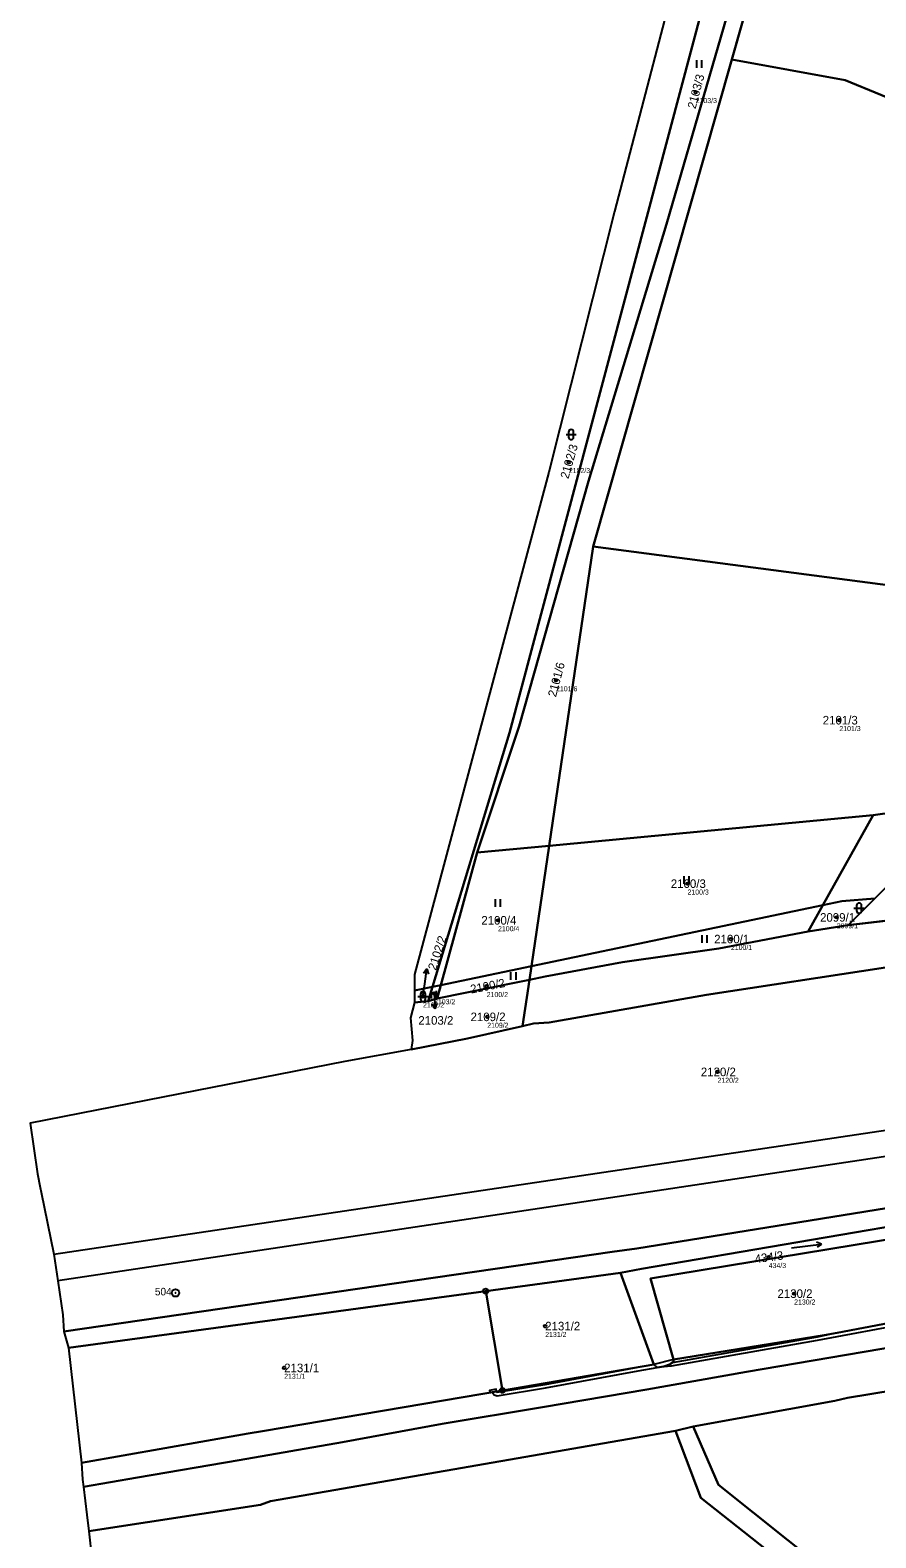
# Model space of a CAD drawing. Extents: x -754731 to -751381, y -1060564 to -1058101.
# Drawn here: x -754402.3 to -754234.5, y -1059330.4 to -1059031.3 of the extents above; entities that cross this region are included whole.
import ezdxf

# ---------------------------------------------------------------- set-up
doc = ezdxf.new("R2010")
doc.units = 0
for name, color, linetype in [('Definiční body', 7, 'Continuous'), ('Hranice parcel', 7, 'Continuous'), ('Parcelní čísla', 7, 'Continuous'), ('Polygon ku', 7, 'Continuous'), ('Polygon parcely', 7, 'Continuous'), ('Pop  PČ popisy', 7, 'Continuous'), ('Poz předměty', 7, 'Continuous'), ('Věcná břemena k části', 7, 'Continuous'), ('Značky bodu BP', 7, 'Continuous'), ('Značky kultur', 7, 'Continuous')]:
    doc.layers.add(name, color=color, linetype=linetype)

msp = doc.modelspace()

# ---------------------------------------------------------------- linework, layer by layer
at = {"layer": 'Definiční body'}
for centre in [(-754270.23, -1059043.64), (-754295.4, -1059117.02), (-754297.93, -1059160.29), (-754241.71, -1059168.19), (-754271.85, -1059200.61), (-754309.45, -1059207.88), (-754242.23, -1059207.3), (-754263.24, -1059211.6), (-754324.34, -1059223), (-754322.15, -1059222.37), (-754311.69, -1059220.94), (-754311.59, -1059227.03), (-754265.89, -1059237.94), (-754255.74, -1059274.68), (-754250.69, -1059281.92), (-754300.09, -1059288.36), (-754351.89, -1059296.65)]:
    msp.add_circle(centre, 0.25, dxfattribs=at)
at = {"layer": 'Hranice parcel'}
for p, q in [((-754263.03, -1059037.17), (-754254.03, -1059005.48)), ((-754263.03, -1059037.17), (-754290.54, -1059133.76)), ((-754290.54, -1059133.76), (-754299.3, -1059193.09)), ((-754235, -1059187), (-754299.3, -1059193.09)), ((-754235, -1059187), (-754244.98, -1059204.86)), ((-754299.3, -1059193.09), (-754313.6, -1059194.45)), ((-754299.3, -1059193.09), (-754302.83, -1059216.97)), ((-754313.6, -1059194.45), (-754320.79, -1059220.73)), ((-754244.98, -1059204.86), (-754302.83, -1059216.97)), ((-754247.92, -1059210.12), (-754244.98, -1059204.86)), ((-754234.68, -1059203.56), (-754239.97, -1059208.82)), ((-754226.15, -1059207.23), (-754239.97, -1059208.82)), ((-754239.97, -1059208.82), (-754247.92, -1059210.12)), ((-754302.83, -1059216.97), (-754320.79, -1059220.73)), ((-754302.83, -1059216.97), (-754303.23, -1059219.67)), ((-754326.05, -1059218.65), (-754326.02, -1059221.83)), ((-754303.23, -1059219.67), (-754304.59, -1059228.85)), ((-754322.45, -1059221.08), (-754326.02, -1059221.83)), ((-754326.02, -1059221.83), (-754326, -1059224.2)), ((-754323.3, -1059223.9), (-754322.45, -1059221.08)), ((-754320.79, -1059220.73), (-754322.45, -1059221.08)), ((-754320.79, -1059220.73), (-754321.51, -1059223.38)), ((-754326, -1059224.2), (-754323.3, -1059223.9)), ((-754323.3, -1059223.9), (-754321.51, -1059223.38)), ((-754326.7, -1059233.52), (-754339.87, -1059235.85)), ((-754339.87, -1059235.85), (-754402.3, -1059248.1)), ((-754400.29, -1059260.85), (-754400.1, -1059261.79)), ((-754311.9, -1059281.41), (-754285.15, -1059277.78)), ((-754285.15, -1059277.78), (-754278.5, -1059296)), ((-754394.66, -1059292.65), (-754311.9, -1059281.41)), ((-754311.9, -1059281.41), (-754308.57, -1059301.11)), ((-754395.79, -1059286.13), (-754395.64, -1059289.45)), ((-754395.64, -1059289.45), (-754394.66, -1059292.65)), ((-754394.66, -1059292.65), (-754392.12, -1059315.49)), ((-754278.5, -1059296), (-754308.57, -1059301.11)), ((-754270.7, -1059308.3), (-754274.2, -1059309.1))]:
    msp.add_line(p, q, dxfattribs=at)
for points in [[(-754259.3, -1058966), (-754271.04, -1059008.8), (-754286.33, -1059067.3), (-754299.4, -1059119), (-754326.05, -1059218.65)], [(-754322.45, -1059221.08), (-754307.2, -1059170.7), (-754252.93, -1058966.94)], [(-754246.61, -1058967.88), (-754248.9, -1058975.5), (-754261.8, -1059020.8), (-754276.05, -1059069.8), (-754291.5, -1059120.8), (-754305.25, -1059169.4), (-754313.6, -1059194.45)], [(-754019.45, -1059118.18), (-754049.17, -1059107.78), (-754115.6, -1059087.15), (-754134.83, -1059085.59), (-754158.57, -1059073.81), (-754175.73, -1059069.12), (-754183.13, -1059057.84), (-754196.56, -1059048.53), (-754203.79, -1059063.52), (-754219.32, -1059050), (-754240.59, -1059041.26), (-754263.03, -1059037.17)], [(-754145.31, -1059167.71), (-754162.03, -1059164.03), (-754187.61, -1059153.26), (-754229.57, -1059141.76), (-754290.54, -1059133.76)], [(-754145.31, -1059167.71), (-754156.78, -1059170.93), (-754188.7, -1059180.8), (-754210.5, -1059183.6), (-754235, -1059187)], [(-754215, -1059193.4), (-754228.6, -1059197.5), (-754234.68, -1059203.56)], [(-754234.68, -1059203.56), (-754241.21, -1059204.07), (-754244.98, -1059204.86)], [(-754141.04, -1059210.29), (-754152.39, -1059210.46), (-754177.1, -1059212.37), (-754232.58, -1059217.23), (-754268.09, -1059222.66), (-754299.29, -1059228.13), (-754302.4, -1059228.35), (-754304.59, -1059228.85)], [(-754303.23, -1059219.67), (-754300.09, -1059219.03), (-754284.78, -1059216.19), (-754265.65, -1059213.48), (-754247.92, -1059210.12)], [(-754321.51, -1059223.38), (-754305.55, -1059220.14), (-754303.23, -1059219.67)], [(-754326, -1059224.2), (-754326.8, -1059227.25), (-754326.4, -1059231.7), (-754326.7, -1059233.52)], [(-754304.59, -1059228.85), (-754315.51, -1059231.32), (-754326.7, -1059233.52)], [(-753994.92, -1059229.37), (-754009.03, -1059236.26), (-754028.95, -1059245.78), (-754072.1, -1059264.36), (-754105.59, -1059276.18), (-754143.83, -1059285.35), (-754183.72, -1059293.33), (-754240.08, -1059302.61), (-754242.58, -1059303.17), (-754270.7, -1059308.3)], [(-754395.64, -1059289.45), (-754286.8, -1059273.6), (-754281.9, -1059273), (-754184.89, -1059257.29), (-754159.27, -1059253.23), (-754150.1, -1059252.43), (-754137.76, -1059249.13), (-754127.95, -1059247.01)], [(-754402.3, -1059248.1), (-754400.84, -1059258.13), (-754400.29, -1059260.85)], [(-754400.1, -1059261.79), (-754397.6, -1059274.1), (-754396.8, -1059279.4), (-754395.79, -1059286.13)], [(-754218.94, -1059266.4), (-754280.99, -1059277), (-754285.15, -1059277.78)], [(-754218.5, -1059268.95), (-754279.2, -1059278.9), (-754274.6, -1059295)], [(-754222.65, -1059285.97), (-754242.14, -1059289.7), (-754244.73, -1059290.17), (-754274.6, -1059295)], [(-754391.74, -1059320.25), (-754381.02, -1059318.4), (-754360.81, -1059314.93), (-754340.34, -1059311.35), (-754320.54, -1059307.74), (-754300.64, -1059304.45), (-754279.95, -1059300.92), (-754260.12, -1059297.43), (-754240.31, -1059294.04), (-754219.65, -1059290.55)], [(-754274.6, -1059295), (-754274.65, -1059295.4), (-754275.4, -1059296), (-754276.57, -1059296.4), (-754277.9, -1059296.6), (-754278.5, -1059296)], [(-754308.57, -1059301.11), (-754356.2, -1059309.2), (-754359.03, -1059309.65), (-754392.12, -1059315.49)], [(-754274.2, -1059309.1), (-754354.6, -1059323.1), (-754356.6, -1059323.8), (-754390.66, -1059329.03)], [(-754274.2, -1059309.1), (-754269.21, -1059322.4), (-754185.4, -1059388.65), (-754163.23, -1059405.65), (-754156.7, -1059409.63), (-754173.89, -1059415.19), (-754189.15, -1059420.39), (-754205.85, -1059428.31), (-754239.13, -1059438.35), (-754268.85, -1059442.06), (-754301.09, -1059445.19), (-754332.05, -1059446.78), (-754377.1, -1059447.2)], [(-754270.7, -1059308.3), (-754265.68, -1059319.84), (-754182.48, -1059386.19), (-754157.97, -1059399.94), (-754148.14, -1059406.2), (-754014.2, -1059355.81)], [(-754392.12, -1059315.49), (-754391.92, -1059318.76), (-754391.74, -1059320.25)], [(-754391.74, -1059320.25), (-754391.08, -1059325.77), (-754390.66, -1059329.03)], [(-754390.66, -1059329.03), (-754385.87, -1059372.37), (-754377.1, -1059447.2)]]:
    msp.add_lwpolyline(points, dxfattribs=at)
at = {"layer": 'Polygon ku'}
msp.add_lwpolyline([(-754271.04, -1059008.8), (-754286.33, -1059067.3), (-754299.4, -1059119), (-754326.05, -1059218.65), (-754326.02, -1059221.83), (-754326, -1059224.2), (-754326.8, -1059227.25), (-754326.4, -1059231.7), (-754326.7, -1059233.52), (-754339.87, -1059235.85), (-754402.3, -1059248.1), (-754400.84, -1059258.13), (-754400.29, -1059260.85), (-754400.1, -1059261.79), (-754397.6, -1059274.1), (-754396.8, -1059279.4), (-754395.79, -1059286.13), (-754395.64, -1059289.45), (-754394.66, -1059292.65), (-754392.12, -1059315.49), (-754391.92, -1059318.76), (-754391.74, -1059320.25), (-754391.08, -1059325.77), (-754390.66, -1059329.03), (-754385.87, -1059372.37)], dxfattribs=at)
at = {"layer": 'Polygon parcely'}
for points in [[(-754326.05, -1059218.65), (-754326.02, -1059221.83), (-754322.45, -1059221.08), (-754307.2, -1059170.7), (-754252.93, -1058966.94), (-754259.3, -1058966), (-754271.04, -1059008.8), (-754286.33, -1059067.3), (-754299.4, -1059119)], [(-754252.93, -1058966.94), (-754307.2, -1059170.7), (-754322.45, -1059221.08), (-754320.79, -1059220.73), (-754313.6, -1059194.45), (-754305.25, -1059169.4), (-754291.5, -1059120.8), (-754276.05, -1059069.8), (-754261.8, -1059020.8), (-754248.9, -1058975.5), (-754246.61, -1058967.88)], [(-754291.5, -1059120.8), (-754305.25, -1059169.4), (-754313.6, -1059194.45), (-754299.3, -1059193.09), (-754290.54, -1059133.76), (-754263.03, -1059037.17), (-754254.03, -1059005.48), (-754243.49, -1058968.34), (-754246.61, -1058967.88), (-754248.9, -1058975.5), (-754261.8, -1059020.8), (-754276.05, -1059069.8)], [(-754019.45, -1059118.18), (-754049.17, -1059107.78), (-754115.6, -1059087.15), (-754134.83, -1059085.59), (-754158.57, -1059073.81), (-754175.73, -1059069.12), (-754183.13, -1059057.84), (-754196.56, -1059048.53), (-754203.79, -1059063.52), (-754219.32, -1059050), (-754240.59, -1059041.26), (-754263.03, -1059037.17), (-754290.54, -1059133.76), (-754229.57, -1059141.76), (-754187.61, -1059153.26), (-754162.03, -1059164.03), (-754145.31, -1059167.71), (-754132, -1059163.98), (-754100.03, -1059153.26), (-754075.72, -1059143.92), (-754054.43, -1059132.52), (-754036.87, -1059123.31), (-754023.46, -1059118.84)], [(-754229.57, -1059141.76), (-754290.54, -1059133.76), (-754299.3, -1059193.09), (-754235, -1059187), (-754210.5, -1059183.6), (-754188.7, -1059180.8), (-754156.78, -1059170.93), (-754145.31, -1059167.71), (-754162.03, -1059164.03), (-754187.61, -1059153.26)], [(-754156.78, -1059170.93), (-754188.7, -1059180.8), (-754210.5, -1059183.6), (-754235, -1059187), (-754244.98, -1059204.86), (-754241.21, -1059204.07), (-754234.68, -1059203.56), (-754228.6, -1059197.5), (-754215, -1059193.4), (-754164.21, -1059178.46), (-754133.34, -1059170.35), (-754145.31, -1059167.71)], [(-754302.83, -1059216.97), (-754244.98, -1059204.86), (-754235, -1059187), (-754299.3, -1059193.09)], [(-754299.3, -1059193.09), (-754313.6, -1059194.45), (-754320.79, -1059220.73), (-754302.83, -1059216.97)], [(-754300.09, -1059219.03), (-754284.78, -1059216.19), (-754265.65, -1059213.48), (-754247.92, -1059210.12), (-754244.98, -1059204.86), (-754302.83, -1059216.97), (-754303.23, -1059219.67)], [(-754234.68, -1059203.56), (-754241.21, -1059204.07), (-754244.98, -1059204.86), (-754247.92, -1059210.12), (-754239.97, -1059208.82)], [(-754321.51, -1059223.38), (-754305.55, -1059220.14), (-754303.23, -1059219.67), (-754302.83, -1059216.97), (-754320.79, -1059220.73)], [(-754326.4, -1059231.7), (-754326.7, -1059233.52), (-754315.51, -1059231.32), (-754304.59, -1059228.85), (-754303.23, -1059219.67), (-754305.55, -1059220.14), (-754321.51, -1059223.38), (-754323.3, -1059223.9), (-754326, -1059224.2), (-754326.8, -1059227.25)], [(-754323.3, -1059223.9), (-754322.45, -1059221.08), (-754326.02, -1059221.83), (-754326, -1059224.2)], [(-754320.79, -1059220.73), (-754322.45, -1059221.08), (-754323.3, -1059223.9), (-754321.51, -1059223.38)], [(-754242.58, -1059303.17), (-754270.7, -1059308.3), (-754265.68, -1059319.84), (-754182.48, -1059386.19), (-754157.97, -1059399.94), (-754148.14, -1059406.2), (-754014.2, -1059355.81), (-753993.55, -1059342.6), (-753987.68, -1059339.52), (-753971.85, -1059332.18), (-753981.35, -1059329.53), (-753981.92, -1059265.91), (-753976.95, -1059263.83), (-753988.16, -1059242.27), (-753994.92, -1059229.37), (-754009.03, -1059236.26), (-754028.95, -1059245.78), (-754072.1, -1059264.36), (-754105.59, -1059276.18), (-754143.83, -1059285.35), (-754183.72, -1059293.33), (-754240.08, -1059302.61)], [(-754093.62, -1059240.35), (-754114.03, -1059243.77), (-754127.95, -1059247.01), (-754137.76, -1059249.13), (-754150.1, -1059252.43), (-754159.27, -1059253.23), (-754184.89, -1059257.29), (-754281.9, -1059273), (-754286.8, -1059273.6), (-754395.64, -1059289.45), (-754394.66, -1059292.65), (-754311.9, -1059281.41), (-754285.15, -1059277.78), (-754280.99, -1059277), (-754218.94, -1059266.4), (-754185.18, -1059260.63), (-754164.68, -1059257.15), (-754120.75, -1059249.32), (-754067.25, -1059235.08), (-754084.06, -1059238.37)], [(-754218.5, -1059268.95), (-754218.94, -1059266.4), (-754280.99, -1059277), (-754285.15, -1059277.78), (-754278.5, -1059296), (-754277.9, -1059296.6), (-754276.57, -1059296.4), (-754275.4, -1059296), (-754274.65, -1059295.4), (-754274.6, -1059295), (-754279.2, -1059278.9)], [(-754222.65, -1059285.97), (-754223.96, -1059279.09), (-754216.97, -1059277.75), (-754218.5, -1059268.95), (-754279.2, -1059278.9), (-754274.6, -1059295), (-754244.73, -1059290.17), (-754242.14, -1059289.7)], [(-754308.57, -1059301.11), (-754278.5, -1059296), (-754285.15, -1059277.78), (-754311.9, -1059281.41)], [(-754392.12, -1059315.49), (-754359.03, -1059309.65), (-754356.2, -1059309.2), (-754308.57, -1059301.11), (-754311.9, -1059281.41), (-754394.66, -1059292.65)], [(-754390.66, -1059329.03), (-754385.87, -1059372.37), (-754377.1, -1059447.2), (-754332.05, -1059446.78), (-754301.09, -1059445.19), (-754268.85, -1059442.06), (-754239.13, -1059438.35), (-754205.85, -1059428.31), (-754189.15, -1059420.39), (-754173.89, -1059415.19), (-754156.7, -1059409.63), (-754163.23, -1059405.65), (-754185.4, -1059388.65), (-754269.21, -1059322.4), (-754274.2, -1059309.1), (-754354.6, -1059323.1), (-754356.6, -1059323.8)]]:
    msp.add_lwpolyline(points, close=True, dxfattribs=at)
for points in [[(-754254.03, -1059005.48), (-754263.03, -1059037.17), (-754240.59, -1059041.26), (-754219.32, -1059050), (-754203.79, -1059063.52), (-754196.56, -1059048.53), (-754183.13, -1059057.84), (-754175.73, -1059069.12), (-754158.57, -1059073.81), (-754134.83, -1059085.59), (-754115.6, -1059087.15), (-754049.17, -1059107.78), (-754019.45, -1059118.18), (-754011.51, -1059116.89), (-753998.98, -1059118.3), (-753983.69, -1059123.33), (-753973.13, -1059127.4), (-753959.82, -1059129.7), (-753949.6, -1059128.98), (-753942.79, -1059128.79), (-753933.27, -1059104.07)], [(-754228.6, -1059197.5), (-754234.68, -1059203.56), (-754239.97, -1059208.82), (-754226.15, -1059207.23)], [(-754226.15, -1059207.23), (-754239.97, -1059208.82), (-754247.92, -1059210.12), (-754265.65, -1059213.48), (-754284.78, -1059216.19), (-754300.09, -1059219.03), (-754303.23, -1059219.67), (-754304.59, -1059228.85), (-754302.4, -1059228.35), (-754299.29, -1059228.13), (-754268.09, -1059222.66), (-754232.58, -1059217.23)], [(-754232.58, -1059217.23), (-754268.09, -1059222.66), (-754299.29, -1059228.13), (-754302.4, -1059228.35), (-754304.59, -1059228.85), (-754315.51, -1059231.32), (-754326.7, -1059233.52), (-754339.87, -1059235.85), (-754402.3, -1059248.1), (-754400.84, -1059258.13), (-754400.29, -1059260.85), (-754400.1, -1059261.79), (-754397.6, -1059274.1), (-754396.8, -1059279.4), (-754395.79, -1059286.13), (-754395.64, -1059289.45), (-754286.8, -1059273.6), (-754281.9, -1059273), (-754184.89, -1059257.29)], [(-754222.65, -1059285.97), (-754242.14, -1059289.7), (-754244.73, -1059290.17), (-754274.6, -1059295), (-754274.65, -1059295.4), (-754275.4, -1059296), (-754276.57, -1059296.4), (-754277.9, -1059296.6), (-754278.5, -1059296), (-754308.57, -1059301.11), (-754356.2, -1059309.2), (-754359.03, -1059309.65), (-754392.12, -1059315.49), (-754391.92, -1059318.76), (-754391.74, -1059320.25), (-754381.02, -1059318.4), (-754360.81, -1059314.93), (-754340.34, -1059311.35), (-754320.54, -1059307.74), (-754300.64, -1059304.45), (-754279.95, -1059300.92), (-754260.12, -1059297.43), (-754240.31, -1059294.04), (-754219.65, -1059290.55)], [(-754219.65, -1059290.55), (-754240.31, -1059294.04), (-754260.12, -1059297.43), (-754279.95, -1059300.92), (-754300.64, -1059304.45), (-754320.54, -1059307.74), (-754340.34, -1059311.35), (-754360.81, -1059314.93), (-754381.02, -1059318.4), (-754391.74, -1059320.25), (-754391.08, -1059325.77), (-754390.66, -1059329.03), (-754356.6, -1059323.8), (-754354.6, -1059323.1), (-754274.2, -1059309.1), (-754270.7, -1059308.3), (-754242.58, -1059303.17), (-754240.08, -1059302.61), (-754183.72, -1059293.33)], [(-754182.48, -1059386.19), (-754265.68, -1059319.84), (-754270.7, -1059308.3), (-754274.2, -1059309.1), (-754269.21, -1059322.4), (-754185.4, -1059388.65)]]:
    msp.add_lwpolyline(points, dxfattribs=at)
at = {"layer": 'Pop  PČ popisy'}
for p, q in [((-754323.58, -1059217.53), (-754324.22, -1059218.45)), ((-754324, -1059220.5), (-754323.58, -1059217.53)), ((-754323.58, -1059217.53), (-754323.23, -1059218.59)), ((-754324.34, -1059223), (-754324, -1059220.5)), ((-754322.15, -1059222.37), (-754322.14, -1059222.45)), ((-754322.14, -1059222.45), (-754321.93, -1059225.44)), ((-754321.93, -1059225.44), (-754322.5, -1059224.48)), ((-754321.93, -1059225.44), (-754321.5, -1059224.41))]:
    msp.add_line(p, q, dxfattribs=at)
at = {"layer": 'Poz předměty'}
for p, q in [((-754397.6, -1059274.1), (-754140.26, -1059235.74)), ((-754139.62, -1059240.72), (-754396.8, -1059279.4))]:
    msp.add_line(p, q, dxfattribs=at)
at = {"layer": 'Věcná břemena k části'}
for points in [[(-754221.37, -1059286.14), (-754232.62, -1059287.88), (-754242.14, -1059289.7), (-754246.15, -1059290.58), (-754274.92, -1059295.62), (-754275.4, -1059296), (-754276.57, -1059296.4), (-754275.04, -1059296.25), (-754246.05, -1059291.18), (-754227.57, -1059287.71), (-754221.15, -1059286.72), (-754220.43, -1059286.24), (-754220.14, -1059285.49), (-754220.85, -1059285.62), (-754220.93, -1059285.84)], [(-754309.76, -1059301.31), (-754310.59, -1059301.45), (-754310.2, -1059302.01), (-754309.65, -1059302.17), (-754300.06, -1059300.58), (-754281.65, -1059297.23), (-754277.9, -1059296.6), (-754278.5, -1059296), (-754300.16, -1059299.98), (-754309.61, -1059301.55)], [(-754274.6, -1059295), (-754278.5, -1059296), (-754277.9, -1059296.6), (-754276.57, -1059296.4), (-754275.4, -1059296), (-754274.92, -1059295.62), (-754274.65, -1059295.4)], [(-754309.76, -1059301.31), (-754309.85, -1059300.84), (-754311.12, -1059301.1), (-754311.03, -1059301.53)]]:
    msp.add_lwpolyline(points, close=True, dxfattribs=at)
at = {"layer": 'Značky bodu BP'}
for centre, radius in [((-754373.45, -1059281.77), 0.75), ((-754373.45, -1059281.77), 0.03), ((-754311.9, -1059281.41), 0.5), ((-754311.9, -1059281.41), 0.0303), ((-754308.57, -1059301.11), 0.5), ((-754308.57, -1059301.11), 0.0303)]:
    msp.add_circle(centre, radius, dxfattribs=at)
at = {"layer": 'Značky kultur'}
for p, q in [((-754269.99, -1059038.79), (-754269.99, -1059037.29)), ((-754268.99, -1059038.79), (-754268.99, -1059037.29)), ((-754295.96, -1059111.54), (-754293.96, -1059111.54)), ((-754295.46, -1059111.04), (-754295.46, -1059112.04)), ((-754294.46, -1059112.04), (-754294.46, -1059111.04)), ((-754272.52, -1059200.65), (-754272.52, -1059199.15)), ((-754271.52, -1059200.65), (-754271.52, -1059199.15)), ((-754309.96, -1059205.18), (-754309.96, -1059203.68)), ((-754308.96, -1059205.18), (-754308.96, -1059203.68)), ((-754238.31, -1059204.95), (-754238.31, -1059205.95)), ((-754237.31, -1059205.95), (-754237.31, -1059204.95)), ((-754238.81, -1059205.45), (-754236.81, -1059205.45)), ((-754268.95, -1059212.33), (-754268.95, -1059210.83)), ((-754267.95, -1059212.33), (-754267.95, -1059210.83)), ((-754306.88, -1059219.66), (-754306.88, -1059218.16)), ((-754305.88, -1059219.66), (-754305.88, -1059218.16)), ((-754325.34, -1059223), (-754323.34, -1059223)), ((-754324.84, -1059222.5), (-754324.84, -1059223.5)), ((-754323.84, -1059223.5), (-754323.84, -1059222.5)), ((-754322.66, -1059223.37), (-754322.66, -1059221.87)), ((-754321.66, -1059223.37), (-754321.66, -1059221.87)), ((-754251.19, -1059272.81), (-754245.23, -1059272.08)), ((-754245.23, -1059272.08), (-754246.27, -1059271.7)), ((-754245.23, -1059272.08), (-754246.14, -1059272.7))]:
    msp.add_line(p, q, dxfattribs=at)
for centre, start, end in [((-754294.96, -1059111.04), 0, 180), ((-754294.96, -1059112.04), 180, 359.9879), ((-754237.81, -1059204.95), 0, 180), ((-754237.81, -1059205.95), 180, 359.9879), ((-754324.34, -1059222.5), 0, 180), ((-754324.34, -1059223.5), 180, 359.9879)]:
    msp.add_arc(centre, 0.5, start, end, dxfattribs=at)

# ---------------------------------------------------------------- texts
at = {"layer": 'Definiční body'}
for s, p in [('2103/3', (-754270.23, -1059045.8)), ('2102/3', (-754295.4, -1059119.18)), ('2101/6', (-754297.93, -1059162.45)), ('2101/3', (-754241.71, -1059170.35)), ('2100/3', (-754271.85, -1059202.77)), ('2100/4', (-754309.45, -1059210.04)), ('2099/1', (-754242.23, -1059209.46)), ('2100/1', (-754263.24, -1059213.76)), ('2100/2', (-754311.69, -1059223.1)), ('2102/2', (-754324.34, -1059225.16)), ('2103/2', (-754322.15, -1059224.53)), ('2109/2', (-754311.59, -1059229.19)), ('2120/2', (-754265.89, -1059240.1)), ('434/3', (-754255.74, -1059276.84)), ('2130/2', (-754250.69, -1059284.08)), ('2131/2', (-754300.09, -1059290.52)), ('2131/1', (-754351.89, -1059298.81))]:
    msp.add_text(s, height=1, dxfattribs=at).set_placement(p)
at = {"layer": 'Parcelní čísla'}
for s, rotation, p in [('2103/3', 75, (-754270.26, -1059047.05)), ('2102/3', 74, (-754295.49, -1059120.43)), ('2101/6', 75, (-754297.96, -1059163.7)), ('2102/2', 72, (-754321.79, -1059217.9)), ('2100/2', 11, (-754314.77, -1059222.41)), ('434/3', 8, (-754258.37, -1059275.91))]:
    msp.add_text(s, height=1.7, rotation=rotation, dxfattribs=at).set_placement(p)
for s, p in [('2101/3', (-754245.02, -1059169.04)), ('2100/3', (-754275.16, -1059201.46)), ('2100/4', (-754312.76, -1059208.73)), ('2099/1', (-754245.54, -1059208.15)), ('2100/1', (-754266.55, -1059212.45)), ('2109/2', (-754314.9, -1059227.88)), ('2103/2', (-754325.27, -1059228.58)), ('2120/2', (-754269.2, -1059238.79)), ('2130/2', (-754253.99, -1059282.77)), ('2131/2', (-754300.09, -1059289.21)), ('2131/1', (-754351.89, -1059297.5))]:
    msp.add_text(s, height=1.7, dxfattribs=at).set_placement(p)
at = {"layer": 'Značky bodu BP'}
msp.add_text('504', height=1.5, dxfattribs=at).set_placement((-754377.55, -1059282.27))

doc.saveas('drawing.dxf')
